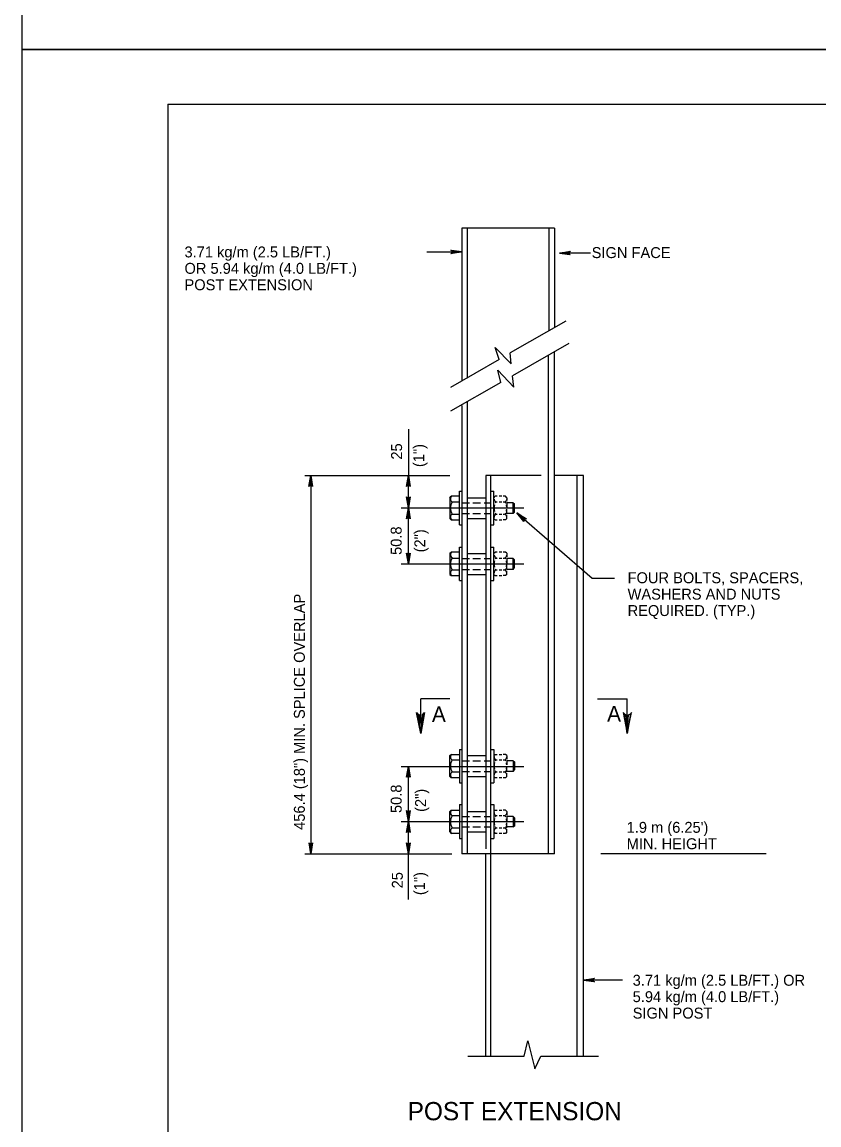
# Model space of a CAD drawing. Extents: x 644358 to 648627, y 294594 to 295782.
# Drawn here: x 644358.3 to 644576.7, y 294892.7 to 295195.1 of the extents above; entities that cross this region are included whole.
import ezdxf

# ---------------------------------------------------------------- set-up
doc = ezdxf.new("R2010")
doc.units = 0
for name, color, linetype in [('1', 7, 'Continuous'), ('2', 7, 'Continuous'), ('3', 7, 'Continuous'), ('4', 7, 'Continuous'), ('PLT-BNDY', 7, 'Continuous')]:
    doc.layers.add(name, color=color, linetype=linetype)

# ---------------------------------------------------------------- blocks, each defined once
blk = doc.blocks.new('RARROW')
at = {"layer": '3'}
blk.add_lwpolyline([(-2.2695, 0.285), (-2.184875, 0.12075), (0, 0), (-2.2695, 0.285), (-2.38575, 0.384625), (0, 0), (-2.183125, -0.108), (-2.262875, -0.2705), (0, 0), (-2.38575, -0.379125), (-2.262875, -0.2705)], dxfattribs=at)

msp = doc.modelspace()

# ---------------------------------------------------------------- linework, layer by layer
at = {"layer": '1'}
for p, q in [((644398.31, 295172.63), (645184.31, 295172.63)), ((644398.31, 295172.63), (644398.31, 294608.63)), ((644491.21, 295064.63), (644491.21, 295063.88)), ((644491.21, 295063.51), (644491.21, 295062.13)), ((644491.21, 295060.26), (644491.21, 295061.51)), ((644491.21, 295059.01), (644491.21, 295060.01)), ((644491.21, 295049.51), (644491.21, 295048.51)), ((644491.21, 295048.13), (644491.21, 295046.76)), ((644491.21, 295045.01), (644491.21, 295046.26)), ((644491.21, 295043.63), (644491.21, 295044.63)), ((644491.21, 294994.01), (644491.21, 294993.01)), ((644491.21, 294992.63), (644491.21, 294991.38)), ((644491.21, 294989.51), (644491.21, 294990.88)), ((644491.21, 294988.26), (644491.21, 294989.13)), ((644491.21, 294978.63), (644491.21, 294977.63)), ((644491.21, 294977.38), (644491.21, 294976.01)), ((644491.21, 294974.13), (644491.21, 294975.51)), ((644491.21, 294973.01), (644491.21, 294973.76))]:
    msp.add_line(p, q, dxfattribs=at)
for points in [[(644468.33, 295005.38), (644467.96, 295005.13), (644467.58, 295000.01), (644468.33, 295005.38), (644468.58, 295005.76), (644467.58, 295000.01), (644467.21, 295005.13), (644466.71, 295005.38), (644467.58, 295000.01), (644466.46, 295005.76), (644466.71, 295005.38)], [(644523.46, 295005.38), (644523.83, 295005.13), (644524.21, 295000.01), (644523.46, 295005.38), (644523.08, 295005.76), (644524.21, 295000.01), (644524.58, 295005.13), (644525.08, 295005.38), (644524.21, 295000.01), (644525.33, 295005.76), (644525.08, 295005.38)]]:
    msp.add_lwpolyline(points, dxfattribs=at)
for centre, radius, start, end in [((644488.49, 295064.34), 0.81, 184.8919, 254.2247), ((644490.72, 295061.85), 3.04, 146.6027, 154.678), ((644490.38, 295064.34), 0.81, 285.7753, 351.6558), ((644488.15, 295061.85), 3.04, 24.9174, 33.3973), ((644490.72, 295061.85), 3.04, 162.8799, 197.6126), ((644488.49, 295059.39), 0.81, 106.5107, 186.623), ((644490.72, 295061.85), 3.04, 205.6812, 213.3973), ((644490.38, 295059.39), 0.81, 358.7185, 73.4893), ((644488.15, 295061.85), 3.04, 326.6027, 334.9746), ((644488.15, 295061.85), 3.04, 6.0459, 16.9125), ((644488.15, 295061.85), 3.04, 344.0189, 354.4846), ((644488.49, 295049.01), 0.81, 184.8919, 254.2247), ((644490.72, 295046.52), 3.04, 146.6027, 154.678), ((644490.38, 295049.01), 0.81, 285.7753, 351.6558), ((644488.15, 295046.52), 3.04, 24.9174, 33.3973), ((644490.72, 295046.52), 3.04, 162.8799, 197.6126), ((644488.49, 295044.05), 0.81, 106.5107, 186.623), ((644490.72, 295046.52), 3.04, 205.6812, 213.3973), ((644490.38, 295044.05), 0.81, 358.7185, 73.4893), ((644488.15, 295046.52), 3.04, 326.6027, 334.9746), ((644488.15, 295046.52), 3.04, 6.0459, 16.9125), ((644488.15, 295046.52), 3.04, 344.0189, 354.4846), ((644488.49, 294993.59), 0.81, 173.377, 253.4893), ((644490.38, 294993.59), 0.81, 286.5107, 1.2815), ((644490.72, 294991.13), 3.04, 162.3874, 197.1201), ((644490.72, 294991.13), 3.04, 146.6027, 154.3188), ((644488.15, 294991.13), 3.04, 25.0254, 33.3973), ((644488.15, 294991.13), 3.04, 343.0875, 353.9541), ((644488.15, 294991.13), 3.04, 5.5154, 15.9811), ((644488.49, 294988.64), 0.81, 105.7753, 175.1081), ((644490.72, 294991.13), 3.04, 205.322, 213.3973), ((644490.38, 294988.64), 0.81, 8.3442, 74.2247), ((644488.15, 294991.13), 3.04, 326.6027, 335.0826), ((644488.49, 294978.26), 0.81, 173.377, 253.4893), ((644490.38, 294978.26), 0.81, 286.5107, 1.2815), ((644490.72, 294975.8), 3.04, 162.3874, 197.1201), ((644490.72, 294975.8), 3.04, 146.6027, 154.3188), ((644488.15, 294975.8), 3.04, 25.0254, 33.3973), ((644488.15, 294975.8), 3.04, 343.0875, 353.9541), ((644488.15, 294975.8), 3.04, 5.5154, 15.9811), ((644488.49, 294973.3), 0.81, 105.7753, 175.1081), ((644490.72, 294975.8), 3.04, 205.322, 213.3973), ((644490.38, 294973.3), 0.81, 8.3442, 74.2247), ((644488.15, 294975.8), 3.04, 326.6027, 335.0826)]:
    msp.add_arc(centre, radius, start, end, dxfattribs=at)
for centre, major_axis, start_param, end_param in [((644478.46, 295061.85), (0, -3.04), 4.129496, 5.295282), ((644476.46, 295064.34), (0, 0.81), 0.448108, 2.866262), ((644476.46, 295059.39), (0, -0.81), 3.429758, 5.835077), ((644478.46, 295046.52), (0, -3.04), 4.129496, 5.295282), ((644476.46, 295049.01), (0, 0.81), 0.448108, 2.866262), ((644476.46, 295044.05), (0, -0.81), 3.429758, 5.835077), ((644476.46, 294993.59), (0, 0.81), 0.448108, 2.853427), ((644478.46, 294991.13), (0, 3.04), 0.987904, 2.153689), ((644476.46, 294988.64), (0, -0.81), 3.416923, 5.835077), ((644476.46, 294978.26), (0, 0.81), 0.448108, 2.853427), ((644478.46, 294975.8), (0, 3.04), 0.987904, 2.153689), ((644476.46, 294973.3), (0, -0.81), 3.416923, 5.835077)]:
    msp.add_ellipse(centre, major_axis=major_axis, ratio=0.9, start_param=start_param, end_param=end_param, dxfattribs=at)
at = {"layer": '2'}
for p, q in [((644504.21, 295138.63), (644478.83, 295138.63)), ((644478.83, 295138.63), (644478.83, 295096.76)), ((644480.33, 295138.63), (644480.33, 295097.51)), ((644502.71, 295138.63), (644502.71, 295110.51)), ((644504.21, 295138.63), (644504.21, 295111.38)), ((644507.33, 295113.13), (644492.08, 295104.38)), ((644508.21, 295107.01), (644492.71, 295098.13)), ((644489.08, 295102.63), (644475.71, 295094.88)), ((644502.58, 294967.01), (644502.58, 295103.76)), ((644504.21, 294967.01), (644504.21, 295104.76)), ((644489.58, 295096.26), (644475.71, 295088.38)), ((644480.33, 295091.01), (644480.33, 294967.01)), ((644478.83, 295090.01), (644478.83, 294967.01)), ((644485.46, 295070.76), (644485.46, 294968.38)), ((644500.58, 295070.76), (644485.46, 295070.76)), ((644486.83, 294911.51), (644486.83, 295070.76)), ((644512.21, 295070.76), (644504.21, 295070.76)), ((644510.46, 294911.51), (644510.46, 295070.76)), ((644512.21, 294911.51), (644512.21, 295070.76)), ((644478.21, 295066.51), (644478.83, 295066.51)), ((644478.21, 295057.26), (644478.21, 295066.51)), ((644486.83, 295066.51), (644487.58, 295066.51)), ((644487.58, 295057.26), (644487.58, 295066.51)), ((644475.58, 295064.63), (644475.96, 295065.13)), ((644475.58, 295064.63), (644475.58, 295059.01)), ((644478.08, 295065.13), (644475.96, 295065.13)), ((644476.21, 295063.51), (644478.08, 295063.51)), ((644478.83, 295063.26), (644480.96, 295063.26)), ((644480.33, 295064.63), (644485.46, 295064.63)), ((644481.83, 295063.26), (644483.96, 295063.26)), ((644484.96, 295063.26), (644486.83, 295063.26)), ((644487.58, 295064.63), (644487.96, 295065.13)), ((644488.58, 295065.13), (644487.96, 295065.13)), ((644488.21, 295063.51), (644488.58, 295063.51)), ((644489.83, 295065.13), (644489.08, 295065.13)), ((644489.08, 295063.51), (644489.83, 295063.51)), ((644490.83, 295065.13), (644490.21, 295065.13)), ((644490.21, 295063.51), (644490.58, 295063.51)), ((644491.21, 295064.63), (644490.83, 295065.13)), ((644492.96, 295063.26), (644491.21, 295063.26)), ((644492.96, 295060.38), (644492.96, 295063.26)), ((644492.96, 295063.26), (644493.33, 295063.01)), ((644493.33, 295060.76), (644493.33, 295063.01)), ((644476.21, 295060.13), (644478.08, 295060.13)), ((644478.83, 295060.38), (644480.96, 295060.38)), ((644481.83, 295060.38), (644483.96, 295060.38)), ((644484.96, 295060.38), (644486.83, 295060.38)), ((644488.21, 295060.13), (644488.58, 295060.13)), ((644489.08, 295060.13), (644489.83, 295060.13)), ((644490.21, 295060.13), (644490.58, 295060.13)), ((644492.96, 295060.38), (644491.21, 295060.38)), ((644492.96, 295060.38), (644493.33, 295060.76)), ((644475.58, 295059.01), (644475.96, 295058.63)), ((644475.96, 295058.63), (644478.08, 295058.63)), ((644478.21, 295057.26), (644478.83, 295057.26)), ((644480.33, 295059.01), (644485.46, 295059.01)), ((644486.83, 295057.26), (644487.58, 295057.26)), ((644487.58, 295059.01), (644487.96, 295058.63)), ((644487.96, 295058.63), (644488.58, 295058.63)), ((644489.08, 295058.63), (644489.83, 295058.63)), ((644490.83, 295058.63), (644490.21, 295058.63)), ((644491.21, 295059.01), (644490.83, 295058.63)), ((644478.21, 295051.13), (644478.83, 295051.13)), ((644478.21, 295042.01), (644478.21, 295051.13)), ((644486.83, 295051.13), (644487.58, 295051.13)), ((644487.58, 295042.01), (644487.58, 295051.13)), ((644475.58, 295049.51), (644475.96, 295049.76)), ((644475.58, 295049.51), (644475.58, 295043.63)), ((644478.08, 295049.76), (644475.96, 295049.76)), ((644476.21, 295048.13), (644478.08, 295048.13)), ((644478.83, 295048.01), (644480.96, 295048.01)), ((644480.33, 295049.38), (644485.46, 295049.38)), ((644481.83, 295048.01), (644483.96, 295048.01)), ((644484.96, 295048.01), (644486.83, 295048.01)), ((644487.58, 295049.51), (644487.96, 295049.76)), ((644488.58, 295049.76), (644487.96, 295049.76)), ((644488.21, 295048.13), (644488.58, 295048.13)), ((644489.83, 295049.76), (644489.08, 295049.76)), ((644489.08, 295048.13), (644489.83, 295048.13)), ((644490.83, 295049.76), (644490.21, 295049.76)), ((644490.21, 295048.13), (644490.58, 295048.13)), ((644491.21, 295049.51), (644490.83, 295049.76)), ((644492.96, 295048.01), (644491.21, 295048.01)), ((644492.96, 295045.01), (644492.96, 295048.01)), ((644492.96, 295048.01), (644493.33, 295047.63)), ((644476.21, 295044.88), (644478.08, 295044.88)), ((644478.83, 295045.01), (644480.96, 295045.01)), ((644481.83, 295045.01), (644483.96, 295045.01)), ((644484.96, 295045.01), (644486.83, 295045.01)), ((644488.21, 295044.88), (644488.58, 295044.88)), ((644489.08, 295044.88), (644489.83, 295044.88)), ((644490.21, 295044.88), (644490.58, 295044.88)), ((644492.96, 295045.01), (644491.21, 295045.01)), ((644492.96, 295045.01), (644493.33, 295045.51)), ((644493.33, 295045.51), (644493.33, 295047.63)), ((644475.58, 295043.63), (644475.96, 295043.38)), ((644475.96, 295043.38), (644478.08, 295043.38)), ((644478.21, 295042.01), (644478.83, 295042.01)), ((644480.33, 295043.63), (644485.46, 295043.63)), ((644486.83, 295042.01), (644487.58, 295042.01)), ((644487.58, 295043.63), (644487.96, 295043.38)), ((644487.96, 295043.38), (644488.58, 295043.38)), ((644489.08, 295043.38), (644489.83, 295043.38)), ((644490.83, 295043.38), (644490.21, 295043.38)), ((644491.21, 295043.63), (644490.83, 295043.38)), ((644475.58, 295009.51), (644467.58, 295009.51)), ((644467.58, 295002.88), (644467.58, 295009.51)), ((644516.08, 295009.51), (644524.21, 295009.51)), ((644524.21, 295002.88), (644524.21, 295009.51)), ((644475.58, 294994.01), (644475.96, 294994.26)), ((644475.58, 294988.26), (644475.58, 294994.01)), ((644475.96, 294994.26), (644478.08, 294994.26)), ((644478.21, 294995.63), (644478.83, 294995.63)), ((644478.21, 294995.63), (644478.21, 294986.51)), ((644480.33, 294994.01), (644485.46, 294994.01)), ((644486.83, 294995.63), (644487.58, 294995.63)), ((644487.58, 294995.63), (644487.58, 294986.51)), ((644487.58, 294994.01), (644487.96, 294994.26)), ((644487.96, 294994.26), (644488.58, 294994.26)), ((644489.08, 294994.26), (644489.83, 294994.26)), ((644490.83, 294994.26), (644490.21, 294994.26)), ((644491.21, 294994.01), (644490.83, 294994.26)), ((644476.21, 294992.76), (644478.08, 294992.76)), ((644478.83, 294992.51), (644480.96, 294992.51)), ((644481.83, 294992.51), (644483.96, 294992.51)), ((644484.96, 294992.51), (644486.83, 294992.51)), ((644488.21, 294992.76), (644488.58, 294992.76)), ((644489.08, 294992.76), (644489.83, 294992.76)), ((644490.21, 294992.76), (644490.58, 294992.76)), ((644492.96, 294992.51), (644491.21, 294992.51)), ((644492.96, 294992.51), (644492.96, 294989.63)), ((644492.96, 294992.51), (644493.33, 294992.26)), ((644493.33, 294992.26), (644493.33, 294990.01)), ((644475.58, 294988.26), (644475.96, 294987.88)), ((644478.08, 294987.88), (644475.96, 294987.88)), ((644476.21, 294989.51), (644478.08, 294989.51)), ((644478.83, 294989.63), (644480.96, 294989.63)), ((644480.33, 294988.26), (644485.46, 294988.26)), ((644481.83, 294989.63), (644483.96, 294989.63)), ((644484.96, 294989.63), (644486.83, 294989.63)), ((644487.58, 294988.26), (644487.96, 294987.88)), ((644488.58, 294987.88), (644487.96, 294987.88)), ((644488.21, 294989.51), (644488.58, 294989.51)), ((644489.08, 294989.51), (644489.83, 294989.51)), ((644489.83, 294987.88), (644489.08, 294987.88)), ((644490.21, 294989.51), (644490.58, 294989.51)), ((644490.83, 294987.88), (644490.21, 294987.88)), ((644491.21, 294988.26), (644490.83, 294987.88)), ((644492.96, 294989.63), (644491.21, 294989.63)), ((644492.96, 294989.63), (644493.33, 294990.01)), ((644478.21, 294986.51), (644478.83, 294986.51)), ((644486.83, 294986.51), (644487.58, 294986.51)), ((644475.58, 294978.63), (644475.96, 294979.01)), ((644475.58, 294973.01), (644475.58, 294978.63)), ((644475.96, 294979.01), (644478.08, 294979.01)), ((644478.21, 294980.51), (644478.83, 294980.51)), ((644478.21, 294980.51), (644478.21, 294971.26)), ((644480.33, 294978.63), (644485.46, 294978.63)), ((644486.83, 294980.51), (644487.58, 294980.51)), ((644487.58, 294980.51), (644487.58, 294971.26)), ((644487.58, 294978.63), (644487.96, 294979.01)), ((644487.96, 294979.01), (644488.58, 294979.01)), ((644489.08, 294979.01), (644489.83, 294979.01)), ((644490.83, 294979.01), (644490.21, 294979.01)), ((644491.21, 294978.63), (644490.83, 294979.01)), ((644476.21, 294977.51), (644478.08, 294977.51)), ((644478.83, 294977.26), (644480.96, 294977.26)), ((644481.83, 294977.26), (644483.96, 294977.26)), ((644484.96, 294977.26), (644486.83, 294977.26)), ((644488.21, 294977.51), (644488.58, 294977.51)), ((644489.08, 294977.51), (644489.83, 294977.51)), ((644490.21, 294977.51), (644490.58, 294977.51)), ((644492.96, 294977.26), (644491.21, 294977.26)), ((644492.96, 294977.26), (644492.96, 294974.38)), ((644492.96, 294977.26), (644493.33, 294976.88)), ((644493.33, 294976.88), (644493.33, 294974.63)), ((644475.58, 294973.01), (644475.96, 294972.63)), ((644478.08, 294972.63), (644475.96, 294972.63)), ((644476.21, 294974.13), (644478.08, 294974.13)), ((644478.83, 294974.38), (644480.96, 294974.38)), ((644480.33, 294973.01), (644485.46, 294973.01)), ((644481.83, 294974.38), (644483.96, 294974.38)), ((644484.96, 294974.38), (644486.83, 294974.38)), ((644487.58, 294973.01), (644487.96, 294972.63)), ((644488.58, 294972.63), (644487.96, 294972.63)), ((644488.21, 294974.13), (644488.58, 294974.13)), ((644489.08, 294974.13), (644489.83, 294974.13)), ((644489.83, 294972.63), (644489.08, 294972.63)), ((644490.21, 294974.13), (644490.58, 294974.13)), ((644490.83, 294972.63), (644490.21, 294972.63)), ((644491.21, 294973.01), (644490.83, 294972.63)), ((644492.96, 294974.38), (644491.21, 294974.38)), ((644492.96, 294974.38), (644493.33, 294974.63)), ((644478.21, 294971.26), (644478.83, 294971.26)), ((644486.83, 294971.26), (644487.58, 294971.26)), ((644504.21, 294967.01), (644478.83, 294967.01)), ((644485.46, 294911.51), (644485.46, 294967.01)), ((644480.46, 294911.51), (644495.96, 294911.51)), ((644500.46, 294911.51), (644516.33, 294911.51))]:
    msp.add_line(p, q, dxfattribs=at)
for points in [[(644489.08, 295102.63), (644487.96, 295105.88), (644492.33, 295101.38), (644492.08, 295104.38)], [(644489.58, 295096.26), (644488.71, 295099.63), (644493.08, 295095.01), (644492.71, 295098.13)], [(644495.96, 294911.51), (644496.96, 294915.76), (644498.83, 294908.01), (644500.46, 294911.51)]]:
    msp.add_lwpolyline(points, dxfattribs=at)
at = {"layer": '4'}
for p, q in [((644469.3, 295132.1), (644478.83, 295132.1)), ((644514.08, 295131.76), (644505.58, 295131.76)), ((644464.21, 295083.48), (644464.21, 295070.76)), ((644435.83, 295070.76), (644475.58, 295070.76)), ((644437.46, 295070.76), (644437.46, 294967.01)), ((644464.21, 295046.51), (644464.21, 295070.76)), ((644462.21, 295061.88), (644495.83, 295061.88)), ((644464.21, 295061.88), (644464.21, 295061.88)), ((644493.96, 295060.51), (644514.58, 295042.63)), ((644462.21, 295046.51), (644495.83, 295046.51)), ((644514.58, 295042.63), (644520.71, 295042.63)), ((644462.21, 294991.01), (644495.83, 294991.01)), ((644464.21, 294975.88), (644464.21, 294991.01)), ((644462.21, 294975.88), (644495.83, 294975.88)), ((644464.21, 294954.5), (644464.21, 294975.88)), ((644435.83, 294967.01), (644476.08, 294967.01)), ((644562.3, 294967.01), (644516.96, 294967.01)), ((644522.93, 294932.38), (644512.21, 294932.38))]:
    msp.add_line(p, q, dxfattribs=at)
at = {"layer": 'PLT-BNDY'}
for points in [[(644358.31, 295781.63), (645199.31, 295781.63), (645199.31, 295187.63), (644358.31, 295187.63)], [(644358.31, 295187.63), (645199.31, 295187.63), (645199.31, 294593.63), (644358.31, 294593.63)]]:
    msp.add_lwpolyline(points, close=True, dxfattribs=at)

# ---------------------------------------------------------------- block references
at = {"layer": '2', "xscale": 1.2574347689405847, "yscale": 1.3092961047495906}
msp.add_blockref('RARROW', (644478.83, 295132.1), dxfattribs=at)
at = {"layer": '2', "xscale": 1.2574347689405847}
for p, yscale, rotation in [((644505.58, 295131.76), 1.3092961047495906, 180), ((644437.46, 295070.76), 1.3092961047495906, 89.99999999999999), ((644464.21, 295070.76), 1.3092961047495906, 89.99999999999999), ((644464.21, 295061.88), 1.3092961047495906, -90.00000000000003), ((644464.21, 295061.88), 1.3092961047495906, 89.99999999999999), ((644493.96, 295060.51), 1.3092961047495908, 138.852656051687), ((644464.21, 295046.51), 1.3092961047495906, -90.00000000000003), ((644464.21, 294991.01), 1.3092961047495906, 89.99999999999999), ((644464.21, 294975.88), 1.3092961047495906, -90.00000000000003), ((644464.21, 294975.88), 1.3092961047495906, 89.99999999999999), ((644437.46, 294967.01), 1.3092961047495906, -90.00000000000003), ((644464.21, 294967.01), 1.3092961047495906, -90.00000000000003), ((644512.21, 294932.38), 1.3092961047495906, 180)]:
    msp.add_blockref('RARROW', p, dxfattribs=dict(at, yscale=yscale, rotation=rotation))

# ---------------------------------------------------------------- texts
at = {"layer": '2'}
msp.add_text('POST EXTENSION', height=5, dxfattribs=at).set_placement((644464, 294893.95))
at = {"layer": '4'}
for s, height, p in [('3.71 kg/m (2.5 LB/FT.)', 3, (644402.83, 295130.58)), (' SIGN FACE', 3, (644513.33, 295130.4)), ('OR 5.94 kg/m (4.0 LB/FT.)', 3, (644402.83, 295126.08)), ('POST EXTENSION', 3, (644402.83, 295121.58)), ('FOUR BOLTS, SPACERS,', 3, (644524.29, 295041.23)), ('WASHERS AND NUTS', 3, (644524.29, 295036.73)), ('REQUIRED. (TYP.)', 3, (644524.29, 295032.23)), ('A', 4.3, (644470.64, 295003.15)), ('A', 4.3, (644518.66, 295003.26)), ("1.9 m (6.25') ", 3, (644524.03, 294972.78)), ('MIN. HEIGHT', 3, (644524.03, 294968.28)), ('3.71 kg/m (2.5 LB/FT.) OR', 3, (644525.68, 294930.84)), ('5.94 kg/m (4.0 LB/FT.)', 3, (644525.68, 294926.34)), ('SIGN POST', 3, (644525.68, 294921.84))]:
    msp.add_text(s, height=height, dxfattribs=at).set_placement(p)
for s, p in [('25 ', (644462.47, 295075.13)), ('(1")', (644468.54, 295073.08)), ('50.8 ', (644462.36, 295048.99)), ('(2")', (644468.85, 295049.7)), ('456.4 (18") MIN. SPLICE OVERLAP', (644435.82, 294973.59)), ('50.8 ', (644462.36, 294978.2)), ('(2")', (644469.04, 294978.52)), ('25 ', (644462.67, 294957.55)), ('(1")', (644468.74, 294955.69))]:
    msp.add_text(s, height=3, rotation=90, dxfattribs=at).set_placement(p)

doc.saveas('drawing.dxf')
